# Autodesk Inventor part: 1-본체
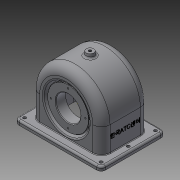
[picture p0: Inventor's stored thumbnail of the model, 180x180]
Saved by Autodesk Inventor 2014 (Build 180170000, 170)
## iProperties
Created: 2015-09
Part Number: 1-본체
Material: 일반
Document SubType Name: Modeling
Designer: Administrator
Density: 1 g/cm^3
Appearance: 기본값
Author: Administrator
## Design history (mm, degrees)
sketch "스케치2"
  geometry: L1 (57, 0)-(-57, 0); L2 (-57, 0)-(-57, -47); L3 (-57, -47)-(57, -47); L4 (57, -47)-(57, 0); A1 r 57 centre (0, 0) between (32.249, -47) and (-32.249, -47); 2 further points
  constraints: 8 end point, 2 coincident, 2 parallel, 2 point on circle, 2 point on line, 1 centre point, 1 horizontal, 1 midpoint, 1 perpendicular, 1 tangent
  dimensions: "d3" = 57 radius of A1; "d4" = 47 distance of L1.end L2.end
extrude "돌출1" new body sketch "스케치2" stored distance "d5" = 77; taper "d6" = 0 deg
sketch "스케치4"
  geometry: L1 (70, -40)-(-70, -40); L2 (-70, -40)-(-70, -47); L3 (-70, -47)-(70, -47); L4 (70, -47)-(70, -40); L5 (-57, -47)-(57, -47) reference; 2 further points
  constraints: 8 end point, 2 parallel, 1 collinear, 1 horizontal, 1 midpoint, 1 perpendicular, 1 vertical alignment
  dimensions: "d9" = 7 distance of L1.end L2.end; "d10" = 140 distance of L2.end L3.end
extrude "돌출2" join sketch "스케치4" stored distance "d11" = 104; taper "d12" = 0 deg
sketch "스케치6"
  geometry: L1 (121, -85.5)-(19, -85.5); L2 (19, -85.5)-(19, -18.5); L3 (19, -18.5)-(121, -18.5); L4 (121, -18.5)-(121, -85.5); L5 (140, -104)-(140, 0) reference; L6 (0, 0)-(140, 0) reference; L7 (0, -104)-(0, 0) reference; L8 (140, -104)-(0, -104) reference; 5 further points
  constraints: 8 end point, 4 midpoint, 2 parallel, 1 horizontal, 1 horizontal alignment, 1 perpendicular, 1 vertical alignment
  dimensions: "d13" = 102 distance of L2.end L3.end; "d14" = 67 distance of L1.end L2.end
extrude "돌출3" cut sketch "스케치6" stored distance "d15" = 104; taper "d16" = 0 deg
sketch "스케치7"
  geometry: L1 (-33.5, 51)-(33.5, 51); L2 (33.5, 51)-(33.5, 0); L3 (33.5, 0)-(-33.5, 0); L4 (-33.5, 0)-(-33.5, 51); L5 (-38.5, 57)-(38.5, 57) reference; 2 further points
  constraints: 8 end point, 2 parallel, 1 coincident, 1 horizontal, 1 midpoint, 1 perpendicular
  dimensions: "d17" = 67 distance of L1.start L1.end; "d18" = 6 distance between parallel lines of L1 L5
revolve "회전1" sketch "스케치7" stored, may be unused: angle "d19" = 90 deg
sketch "스케치8"
  geometry: C1 r 31 at (0, 0); 1 further point
  constraints: 1 centre point, 1 coincident
  dimensions: "d20" = 62 diameter of C1
extrude "돌출4" join sketch "스케치8" distance "d21" = 10; taper "d22" = 0 deg
node "작업 평면3"
  node "작업 평면2"
sketch "스케치12"
  geometry: 1 further point
sketch "스케치13"
  geometry: C1 r 28 at (0, 0); 1 further point
  constraints: 1 centre point, 1 coincident
  dimensions: "d25" = 56 diameter of C1
extrude "돌출5" join sketch "스케치13" stored distance "d26" = 10; taper "d27" = 40 deg
sketch "스케치15"
  geometry: L1 (-19.5, 28)-(-33.5, 39.747) reference; L2 (-38.5, 57)-(-38.5, 0) reference; L3 (-35.5, 33)-(-33.237, 33); L4 (-35.5, 0)-(-35.5, 33); L5 (-38.5, 0)-(-35.5, 0); L6 (-33.237, 33)-(-38.5, 37.416); 1 further point
  constraints: 8 end point, 1 parallel, 1 perpendicular, 1 point on line, 1 vertical
  dimensions: "d31" = 3 distance between parallel lines of L2 L4; "d88" = 5 distance between parallel lines of L6 L1; "d89" = 66 diameter of L3 L5
revolve "회전2" sketch "스케치15" stored, may be unused: angle "d32" = 90 deg
hole "구멍1" diameter "d36" = 40; stored, may be unused: countersink angle "d40" = 90 deg, drill point angle "d42" = 0 deg; dims "d34" = 10, "d35" = 10, "d37" = 6, "d38" = 4, "d39" = 2, "d41" = 8
hole "구멍2" diameter "d45" = 40; stored, may be unused: countersink angle "d49" = 90 deg, drill point angle "d51" = 0 deg; dims "d43" = 10, "d44" = 10, "d46" = 6, "d47" = 4, "d48" = 2, "d50" = 8
node "작업 평면4"
sketch "스케치17"
  geometry: C1 r 6 at (0, 0); 1 further point
  constraints: 1 centre point, 1 coincident
  dimensions: "d53" = 12 diameter of C1
extrude "돌출6" join sketch "스케치17" stored distance "d54" = 10; taper "d55" = 10 deg
sketch "스케치18"
  geometry: L1 (0, 0)-(0, 28); C1 r 20 at (0, 0) reference; 2 further points
  constraints: 2 end point, 1 coincident, 1 vertical
  dimensions: "d57" = 28 distance of L1.start L1.end
hole "구멍3" sketch "스케치18" at (0, 28) diameter "d58" = 2.459; stored, may be unused: countersink angle "d62" = 90 deg, drill point angle "d64" = 118 deg; dims "d59" = 7, "d60" = 4, "d61" = 2, "d63" = 9
sketch "스케치19"
  geometry: L1 (0, 0)-(0, -24); C1 r 31 at (0, 0) reference; 2 further points
  constraints: 2 end point, 1 coincident, 1 vertical
  dimensions: "d68" = 24 distance of L1.start L1.end
hole "구멍4" sketch "스케치19" at (0, -24) diameter "d69" = 2.459; stored, may be unused: countersink angle "d73" = 90 deg, drill point angle "d75" = 118 deg; dims "d70" = 6, "d71" = 4, "d72" = 2, "d74" = 8
hole "구멍5" diameter "d81" = 4.459; stored, may be unused: countersink angle "d85" = 90 deg, drill point angle "d87" = 0 deg; dims "d82" = 6, "d83" = 4, "d84" = 2, "d86" = 8, "d123" = 10, "d124" = 10
fillet "모깎기2" dims "d90" = 3
sketch "스케치21"
  geometry: L1 (0, 104)-(0, 0) reference; L2 (140, 0)-(0, 0) reference; 2 further points
  dimensions: "d91" = 8 distance from line of L1 point (8, 8); "d92" = 8 distance from line of L2 point (8, 8)
hole "구멍6" sketch "스케치21" at (8, 8) diameter "d93" = 5; stored, may be unused: countersink angle "d97" = 90 deg, drill point angle "d99" = 0 deg; dims "d94" = 6, "d95" = 4, "d96" = 2, "d98" = 8
fillet "모깎기3" dims "d103" = 7
fillet "모깎기5" dims "d105" = 3
fillet "모깎기6" dims "d106" = 3
chamfer "모따기1" distance "d107" = 1; stored, may be unused: second distance "d108" = 2, angle "d109" = 45 deg
fillet "모깎기7" dims "d113" = 9
fillet "모깎기8" dims "d114" = 14
fillet "모깎기9" dims "d115" = 1
fillet "모깎기10" dims "d116" = 0.5
fillet "모깎기11" dims "d117" = 3
sketch "스케치22"
  geometry: L1 (29.508, -7.81)-(29.508, 56.81); L2 (29.508, 56.81)-(4.492, 56.81); L3 (4.492, 56.81)-(4.492, -7.81); L4 (4.492, -7.81)-(29.508, -7.81); L5 (47, -20.5)-(47, 69.5) reference; L6 (0, 0)-(0, 49) reference; 4 further points
  constraints: 3 midpoint, 1 horizontal, 1 horizontal alignment, 2 other
  dimensions: "d118" = 30 distance from line of L5 point (17, -7.81)
feature "엠보싱1" sketch "스케치22" dims "d3" = 57, "d4" = 47, "d119" = 0.5, "d120" = 0
node "솔리드1"
pattern_circular "원형 패턴2" dims angle "d77" = 360 deg
pattern_linear "직사각형 패턴1" dims "d102" = 44
mirror "대칭1"
pattern_circular "원형 패턴3" dims angle "d111" = 360 deg
node "투영된 루프1"
other parameters: "d23" = 0, "d24" = -19, "d29" = 3, "d52" = 63
